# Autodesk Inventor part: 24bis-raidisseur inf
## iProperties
Created: 2011-02
Part Number: 24bis-raidisseur inf
Document SubType Name: Modeling
Designer: eric
Density: 1 g/cm^3
Author: eric
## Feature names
1. Base1
